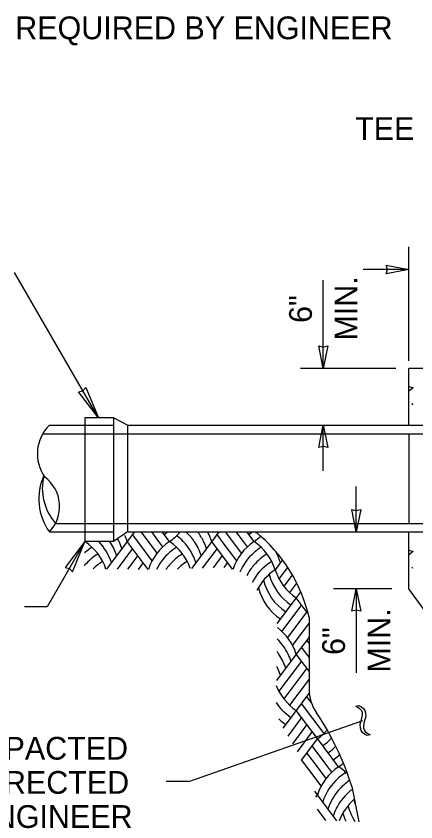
# Model space of a CAD drawing. Extents: x 99862 to 103151, y 100000 to 102076.
# Drawn here: x 101648 to 101929, y 100997 to 101564 of the extents above; entities that cross this region are included whole.
import ezdxf

# ---------------------------------------------------------------- set-up
doc = ezdxf.new("R2010")
doc.units = 0
for name, color, linetype in [('Level 1', 7, 'Continuous'), ('Level 15', 7, 'Continuous'), ('Level 17', 7, 'Continuous'), ('Level 19', 7, 'Continuous'), ('Level 20', 7, 'Continuous'), ('Level 28', 7, 'Continuous'), ('Level 6', 7, 'Continuous')]:
    doc.layers.add(name, color=color, linetype=linetype)

msp = doc.modelspace()

# ---------------------------------------------------------------- linework, layer by layer
at = {"layer": 'Level 1'}
for p, q in [((101716.16, 101281.22), (101696.16, 101281.22)), ((101696.16, 101281.22), (101696.16, 101194.22)), ((101716.16, 101281.22), (101716.16, 101194.22)), ((101726.16, 101275.98), (101716.16, 101281.22)), ((101671.16, 101275.98), (101696.16, 101275.98)), ((101726.16, 101275.98), (101726.16, 101200.98)), ((101726.16, 101275.98), (101934.47, 101275.98)), ((101923.66, 101269.98), (101923.66, 101206.98)), ((101671.16, 101200.98), (101696.16, 101200.98)), ((101726.16, 101200.98), (101716.16, 101194.22)), ((101726.16, 101200.98), (101934.47, 101200.98)), ((101716.16, 101194.22), (101696.16, 101194.22))]:
    msp.add_line(p, q, dxfattribs=at)
for centre, radius, start, end in [((101690.83, 101255.9), 28.12, 134.4143, 215.6362), ((101703.78, 101224.23), 40.06, 155.8391, 215.4815), ((101704.29, 101231.87), 38.09, 166.7032, 220.7986), ((101652.58, 101218.85), 25.78, 316.1175, 53.2995)]:
    msp.add_arc(centre, radius, start, end, dxfattribs=at)
at = {"layer": 'Level 15'}
for p, q in [((101923.66, 101321.34), (101923.66, 101401.45)), ((101705.61, 101281.22), (101646.63, 101383.38)), ((101923.66, 101385.45), (101891.66, 101385.45)), ((101863.66, 101315.98), (101863.66, 101377.94)), ((101914.6, 101315.98), (101847.67, 101315.98)), ((101863.66, 101243.98), (101863.66, 101275.98)), ((101886.85, 101200.98), (101886.85, 101232.98)), ((101696.16, 101194.22), (101669.68, 101148.36)), ((101911.79, 101160.98), (101870.85, 101160.98)), ((101886.85, 101160.98), (101886.85, 101101.84)), ((101669.68, 101148.36), (101653.68, 101148.36)), ((101769.18, 101025.4), (101891.51, 101068.4)), ((101769.18, 101025.4), (101753.18, 101025.4))]:
    msp.add_line(p, q, dxfattribs=at)
for points in [[(101923.66, 101385.45), (101907.93, 101382.36), (101908.66, 101385.45), (101907.93, 101388.53)], [(101863.66, 101315.98), (101860.57, 101331.71), (101863.66, 101330.98), (101866.74, 101331.71)], [(101705.61, 101281.22), (101691.61, 101299.5), (101694.72, 101300.08), (101696.78, 101302.49)], [(101863.66, 101275.98), (101866.74, 101260.26), (101863.66, 101260.99), (101860.57, 101260.26)], [(101886.85, 101200.98), (101883.77, 101216.71), (101886.85, 101215.98), (101889.94, 101216.71)], [(101696.16, 101194.22), (101682.16, 101175.95), (101685.27, 101175.37), (101687.33, 101172.96)], [(101886.85, 101160.98), (101889.94, 101145.26), (101886.85, 101145.99), (101883.77, 101145.26)]]:
    msp.add_lwpolyline(points, close=True, dxfattribs=at)
at = {"layer": 'Level 17'}
for p, q in [((102147.16, 101315.98), (101923.66, 101315.98)), ((101923.66, 101275.98), (101923.66, 101315.98)), ((101816.77, 101200.35), (101816.01, 101200.35)), ((101923.66, 101160.98), (101923.66, 101200.98)), ((101968.66, 101098.98), (101923.66, 101160.98)), ((101853.66, 101140.98), (101853.66, 101090.6)), ((101883.66, 101021.98), (101888.5, 100997.24))]:
    msp.add_line(p, q, dxfattribs=at)
for centre, radius, start, end in [((101747.23, 101116.19), 109.28, 13.1159, 50.8949), ((101883.66, 101090.6), 30, 180, 214.2474), ((101700.95, 100966.21), 191.03, 16.9759, 34.2474)]:
    msp.add_arc(centre, radius, start, end, dxfattribs=at)
at = {"layer": 'Level 19'}
for p, q in [((101925.88, 101291.4), (101926.38, 101290.39)), ((101925.88, 101176.4), (101926.38, 101175.39))]:
    msp.add_line(p, q, dxfattribs=at)
for points in [[(101923.66, 101302.69), (101923.7, 101303.17), (101926.68, 101302.27), (101923.66, 101299.96)], [(101923.66, 101187.69), (101923.7, 101188.17), (101926.68, 101187.27), (101923.66, 101184.96)]]:
    msp.add_lwpolyline(points, dxfattribs=at)
at = {"layer": 'Level 20'}
for p, q in [((101886.5, 101078.47), (101888.57, 101078.9)), ((101889.57, 101076.42), (101886.5, 101078.47)), ((101888.56, 101078.9), (101890.46, 101077.9)), ((101890.63, 101075.16), (101889.57, 101076.42)), ((101890.46, 101077.9), (101891.84, 101076.77)), ((101891.84, 101076.77), (101892.77, 101075.45)), ((101892.77, 101075.45), (101893.31, 101073.88)), ((101889.65, 101065.69), (101890.67, 101069.98)), ((101891.16, 101073.84), (101890.63, 101075.16)), ((101890.67, 101069.98), (101891.23, 101072.34)), ((101891.23, 101072.34), (101891.16, 101073.84)), ((101893.44, 101071.42), (101892.42, 101067.46)), ((101893.31, 101073.88), (101893.44, 101071.42)), ((101889.73, 101062.97), (101889.65, 101065.69)), ((101892.42, 101067.46), (101891.84, 101064.97)), ((101891.84, 101064.97), (101891.87, 101063.05)), ((101890.31, 101061.31), (101889.73, 101062.97)), ((101891.29, 101059.92), (101890.31, 101061.31)), ((101892.69, 101058.79), (101891.29, 101059.92)), ((101891.87, 101063.05), (101892.32, 101061.8)), ((101892.32, 101061.8), (101893.11, 101060.69)), ((101894.48, 101057.93), (101892.69, 101058.79)), ((101893.11, 101060.69), (101894.46, 101059.59)), ((101894.46, 101059.59), (101896.55, 101058.36)), ((101896.55, 101058.36), (101894.48, 101057.93))]:
    msp.add_line(p, q, dxfattribs=at)
at = {"layer": 'Level 28'}
for p, q in [((101730.93, 101200.98), (101725.86, 101194.22)), ((101740.71, 101194.22), (101735.64, 101200.98)), ((101748.13, 101194.22), (101743.06, 101200.98)), ((101755.55, 101194.22), (101750.48, 101200.98)), ((101782.9, 101200.98), (101782.58, 101200.56)), ((101790.32, 101200.98), (101785.25, 101194.22)), ((101800.1, 101194.22), (101795.03, 101200.98)), ((101807.53, 101194.22), (101802.46, 101200.98)), ((101814.95, 101194.22), (101809.88, 101200.98)), ((101725.86, 101194.22), (101711.33, 101174.85)), ((101740.6, 101174.57), (101725.86, 101194.22)), ((101733.28, 101194.22), (101729.57, 101199.17)), ((101743.38, 101180.76), (101733.28, 101194.22)), ((101746.82, 101186.07), (101740.71, 101194.22)), ((101750.9, 101190.53), (101748.13, 101194.22)), ((101785.25, 101194.22), (101770.96, 101175.16)), ((101799.89, 101174.71), (101785.25, 101194.22)), ((101792.68, 101194.22), (101788.96, 101199.17)), ((101802.78, 101180.76), (101792.68, 101194.22)), ((101806.22, 101186.07), (101800.1, 101194.22)), ((101810.3, 101190.53), (101807.53, 101194.22)), ((101729.57, 101189.27), (101718.7, 101174.78)), ((101788.96, 101189.27), (101778.59, 101175.44)), ((101733.28, 101184.33), (101726.07, 101174.71)), ((101792.68, 101184.33), (101786.22, 101175.71)), ((101736.99, 101179.38), (101733.44, 101174.63)), ((101796.39, 101179.38), (101793.85, 101175.99)), ((101834.76, 101181.04), (101829.8, 101174.43)), ((101838.45, 101176.06), (101832.47, 101168.09)), ((101841.78, 101170.6), (101835.92, 101162.78)), ((101844.88, 101164.84), (101839.99, 101158.32)), ((101844.65, 101154.63), (101831.04, 101136.49)), ((101847.39, 101158.29), (101844.65, 101154.63)), ((101852.41, 101144.27), (101844.65, 101154.63)), ((101848.36, 101149.68), (101834.45, 101131.13)), ((101852.07, 101144.73), (101838.53, 101126.67)), ((101853.66, 101136.94), (101841.97, 101121.36)), ((101853.66, 101127.04), (101844.65, 101115.03)), ((101853.66, 101122.81), (101852.07, 101124.93)), ((101844.65, 101115.03), (101830.7, 101096.43)), ((101853.66, 101103.02), (101844.65, 101115.03)), ((101852.07, 101115.03), (101848.36, 101119.98)), ((101853.66, 101112.91), (101852.07, 101115.03)), ((101848.36, 101110.08), (101832.47, 101088.9)), ((101852.07, 101105.13), (101835.92, 101083.59)), ((101853.66, 101097.34), (101839.99, 101079.12)), ((101854.05, 101087.97), (101844.65, 101075.43)), ((101855.42, 101080.87), (101852.07, 101085.33)), ((101844.65, 101075.43), (101835.32, 101063)), ((101859.5, 101055.63), (101844.65, 101075.43)), ((101864.15, 101059.33), (101848.36, 101080.38)), ((101848.36, 101070.48), (101838.61, 101057.48)), ((101852.07, 101065.53), (101841.89, 101051.96)), ((101855.79, 101060.58), (101845.18, 101046.44)), ((101859.5, 101055.63), (101848.15, 101040.51)), ((101874.35, 101035.83), (101859.5, 101055.63)), ((101866.92, 101035.83), (101855.79, 101050.68)), ((101859.5, 101035.83), (101852.07, 101045.73)), ((101852.07, 101035.83), (101848.36, 101040.78)), ((101862.17, 101022.37), (101852.07, 101035.83)), ((101865.62, 101027.68), (101859.5, 101035.83)), ((101869.69, 101032.14), (101866.92, 101035.83)), ((101859.5, 101016.03), (101857.58, 101018.59)), ((101859.5, 101016.03), (101858.25, 101014.37)), ((101873.15, 100997.83), (101859.5, 101016.03)), ((101865.51, 100998.12), (101859.56, 101006.05))]:
    msp.add_line(p, q, dxfattribs=at)
for centre, start, end in [((101730.88, 101230.36), 303.9036, 308.574), ((101734.59, 101225.41), 303.9036, 319.4522), ((101742.02, 101172.94), 34.5089, 48.282), ((101745.73, 101177.89), 25.7734, 37.9307), ((101749.44, 101182.84), 17.6434, 28.8806), ((101790.28, 101230.36), 303.9036, 308.574), ((101675.2, 101163.04), 56.0955, 56.0964), ((101675.2, 101163.04), 18.3303, 56.0955), ((101717.12, 101163.04), 123.9037, 123.9045), ((101678.91, 101167.99), 17.6434, 44.2873), ((101682.62, 101172.94), 17.6434, 34.509), ((101686.33, 101177.89), 25.7734, 28.6154), ((101686.33, 101177.89), 17.6434, 25.7735), ((101690.05, 101182.84), 17.6434, 24.5563), ((101776.52, 101163.04), 123.9037, 162.1351), ((101734.59, 101163.04), 18.7811, 56.0964), ((101738.31, 101167.99), 44.2872, 53.669), ((101738.31, 101167.99), 17.6434, 44.2873), ((101742.02, 101172.94), 17.6434, 34.509), ((101745.73, 101177.89), 17.6434, 25.7735), ((101835.91, 101163.04), 123.9037, 162.0811), ((101793.99, 101225.41), 303.9036, 313.102), ((101793.99, 101163.04), 17.6434, 56.0964), ((101720.83, 101158.09), 121.4535, 131.0403), ((101780.23, 101158.09), 121.4535, 131.0403), ((101839.62, 101158.09), 121.4535, 131.0403), ((101720.83, 101158.09), 131.0403, 131.5989), ((101724.54, 101153.14), 120.6979, 139.0587), ((101780.23, 101158.09), 131.0403, 154.0856), ((101783.94, 101153.14), 120.6979, 139.0587), ((101839.62, 101158.09), 131.0403, 157.3296), ((101843.34, 101153.14), 120.6979, 139.0587), ((101797.7, 101167.99), 17.6434, 30.2119), ((101724.54, 101153.14), 139.0586, 140.4436), ((101728.26, 101148.19), 121.5126, 134.6035), ((101783.94, 101153.14), 139.0586, 145.3254), ((101787.65, 101148.19), 121.5126, 134.8934), ((101843.34, 101153.14), 139.0586, 152.5799), ((101847.05, 101148.19), 121.5126, 148.6684), ((101850.76, 101143.24), 123.9036, 153.92), ((101865.61, 101185.81), 197.6434, 236.0964), ((101847.05, 101148.19), 148.6683, 152.7993), ((101858.18, 101175.92), 193.6801, 236.0964), ((101861.9, 101180.87), 194.9887, 236.0964), ((101854.47, 101170.97), 194.2287, 236.0964), ((101808.84, 101103.64), 17.6434, 53.131), ((101805.13, 101098.69), 25.7734, 45.9825), ((101801.41, 101093.74), 34.5089, 37.8778), ((101801.41, 101093.74), 17.6434, 34.509), ((101805.13, 101098.69), 17.6434, 25.7735), ((101797.7, 101088.79), 17.6434, 27.9885), ((101865.61, 101106.62), 201.4548, 236.0964), ((101861.9, 101101.67), 213.1079, 236.0964), ((101858.18, 101096.72), 226.5013, 236.0964), ((101838.54, 101086.82), 303.9036, 318.2304), ((101842.25, 101081.87), 303.9036, 316.5201), ((101845.96, 101076.92), 303.9036, 314.8277), ((101849.67, 101071.97), 303.9036, 311.0401), ((101849.67, 101071.97), 311.0401, 312.3224), ((101895.31, 101004.64), 123.9037, 162.3566), ((101853.39, 101067.02), 303.9036, 309.5723), ((101853.39, 101004.64), 44.8318, 56.0964), ((101899.02, 100999.69), 121.4535, 131.0403), ((101899.02, 100999.69), 131.0403, 162.3566), ((101902.73, 100994.74), 123.434, 139.0587), ((101902.73, 100994.74), 139.0586, 162.3566), ((101906.44, 100989.79), 126.5765, 148.6684), ((101910.16, 100984.85), 131.2203, 159.8896), ((101906.44, 100989.79), 148.6683, 162.3566), ((101917.58, 101017.52), 193.6801, 212.4793), ((101921.29, 101022.47), 194.9887, 200.8753), ((101913.87, 101012.57), 194.2287, 203.4962)]:
    msp.add_arc(centre, 37.58, start, end, dxfattribs=at)
at = {"layer": 'Level 6'}
for p, q in [((101696.16, 101275.98), (101716.16, 101275.98)), ((101666.5, 101269.98), (102171.16, 101269.98)), ((101675.46, 101206.98), (102011.66, 101206.98)), ((101696.16, 101200.98), (101716.16, 101200.98))]:
    msp.add_line(p, q, dxfattribs=at)

# ---------------------------------------------------------------- texts
at = {"layer": 'Level 20'}
for s, p in [('REQUIRED BY ENGINEER', (101647.19, 101547.39)), ('TEE', (101886.03, 101476.53))]:
    msp.add_text(s, height=16, dxfattribs=at).set_placement(p)
for s, rotation, p in [('MIN.', 90, (101887.61, 101335.55)), ('6"', 90, (101855.61, 101347.91)), ('MIN.', 90, (101910.85, 101102.07)), ('6"', 90, (101878.85, 101114.44)), ('BACKFILL WITH COMPACTED', 360, (101422.13, 101040.86)), ('MATERIAL AS DIRECTED', 360, (101470.42, 101016.86)), ('BY ENGINEER', 360, (101583.36, 100992.86))]:
    msp.add_text(s, height=16, rotation=rotation, dxfattribs=at).set_placement(p)

doc.saveas('drawing.dxf')
